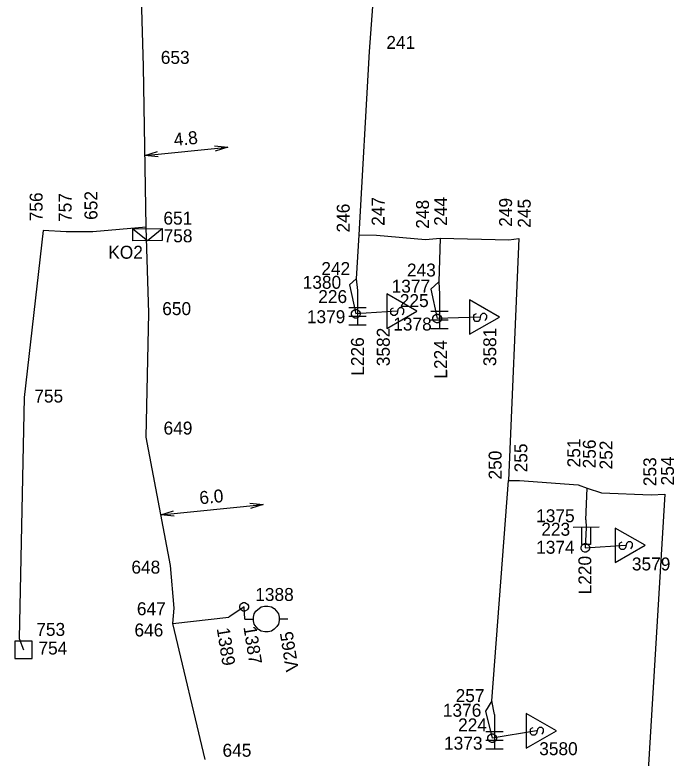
# Model space of a CAD drawing. Extents: x -535557 to -534097, y -1142175 to -1136716.
# Drawn here: x -534537.76 to -534499.53, y -1140603.81 to -1140560.72 of the extents above; entities that cross this region are included whole.
import ezdxf

# ---------------------------------------------------------------- set-up
doc = ezdxf.new("R2010")
doc.units = 0
doc.layers.add('Default', color=7, linetype='Continuous')
doc.layers.add('SS_SZDC', color=7, linetype='Continuous')

# ---------------------------------------------------------------- blocks, each defined once
blk = doc.blocks.new('POINT_DISPLAY')
at = {"layer": 'Default'}
blk.add_line((0, 0), (0, 0), dxfattribs=at)

msp = doc.modelspace()

# ---------------------------------------------------------------- linework, layer by layer
at = {"layer": 'SS_SZDC'}
for p, q in [((-534516.34, -1140551.12), (-534517.22, -1140562.84)), ((-534530.3, -1140563.709), (-534530.6, -1140554.11)), ((-534517.22, -1140562.84), (-534517.819, -1140573.469)), ((-534530.149, -1140573.03), (-534530.3, -1140563.709)), ((-534530.216, -1140568.872), (-534525.42, -1140568.396)), ((-534526.182, -1140568.32), (-534525.42, -1140568.396)), ((-534525.42, -1140568.396), (-534526.152, -1140568.619)), ((-534530.216, -1140568.872), (-534529.485, -1140568.648)), ((-534529.455, -1140568.947), (-534530.216, -1140568.872)), ((-534530.149, -1140573.03), (-534533.239, -1140573.29)), ((-534530.922, -1140573.115), (-534529.222, -1140573.104)), ((-534530.917, -1140573.815), (-534530.922, -1140573.115)), ((-534530.922, -1140573.115), (-534530.067, -1140573.809)), ((-534530, -1140578.01), (-534530.149, -1140573.03)), ((-534530.067, -1140573.809), (-534529.222, -1140573.104)), ((-534529.222, -1140573.104), (-534529.217, -1140573.804)), ((-534536.13, -1140573.219), (-534537.229, -1140582.909)), ((-534534.779, -1140573.29), (-534536.13, -1140573.219)), ((-534533.239, -1140573.29), (-534534.779, -1140573.29)), ((-534517.819, -1140573.469), (-534517.96, -1140576.02)), ((-534517.819, -1140573.469), (-534516.8, -1140573.489)), ((-534516.8, -1140573.489), (-534513.949, -1140573.75)), ((-534529.217, -1140573.804), (-534530.917, -1140573.815)), ((-534513.949, -1140573.75), (-534513.09, -1140573.67)), ((-534513.09, -1140573.67), (-534513.17, -1140576.19)), ((-534513.09, -1140573.67), (-534509.119, -1140573.76)), ((-534508.539, -1140573.68), (-534509.13, -1140587.719)), ((-534509.119, -1140573.76), (-534508.539, -1140573.68)), ((-534517.96, -1140576.02), (-534518.359, -1140576.36)), ((-534517.96, -1140576.02), (-534517.899, -1140576.7)), ((-534518.359, -1140576.36), (-534517.989, -1140578.049)), ((-534513.17, -1140576.19), (-534513.64, -1140576.629)), ((-534513.17, -1140576.19), (-534513.14, -1140576.92)), ((-534517.899, -1140576.7), (-534517.899, -1140578.7)), ((-534516.2, -1140576.899), (-534516.2, -1140578.899)), ((-534514.45, -1140577.899), (-534516.2, -1140576.899)), ((-534513.64, -1140576.629), (-534513.27, -1140578.319)), ((-534513.14, -1140576.92), (-534513.14, -1140578.92)), ((-534511.4, -1140577.239), (-534511.4, -1140579.239)), ((-534509.65, -1140578.239), (-534511.4, -1140577.239)), ((-534517.399, -1140577.7), (-534518.399, -1140577.7)), ((-534518.19, -1140577.901), (-534518.141, -1140577.85)), ((-534518.141, -1140577.85), (-534518.041, -1140577.8)), ((-534518.041, -1140577.8), (-534517.941, -1140577.799)), ((-534515.6, -1140577.899), (-534517.989, -1140578.049)), ((-534517.941, -1140577.799), (-534517.841, -1140577.849)), ((-534517.841, -1140577.849), (-534517.79, -1140577.898)), ((-534517.79, -1140577.898), (-534517.74, -1140577.998)), ((-534516.2, -1140578.899), (-534514.45, -1140577.899)), ((-534515.95, -1140577.799), (-534515.9, -1140577.749)), ((-534515.95, -1140578.049), (-534515.95, -1140577.799)), ((-534515.9, -1140577.749), (-534515.8, -1140577.699)), ((-534515.55, -1140577.799), (-534515.6, -1140578.049)), ((-534515.45, -1140577.699), (-534515.55, -1140577.799)), ((-534515.3, -1140577.699), (-534515.45, -1140577.699)), ((-534515.2, -1140577.799), (-534515.3, -1140577.699)), ((-534515.2, -1140577.949), (-534515.2, -1140577.799)), ((-534530.14, -1140585.2), (-534530, -1140578.01)), ((-534517.399, -1140578.2), (-534518.399, -1140578.2)), ((-534518.24, -1140578.001), (-534518.19, -1140577.901)), ((-534518.239, -1140578.101), (-534518.24, -1140578.001)), ((-534518.189, -1140578.201), (-534518.239, -1140578.101)), ((-534518.138, -1140578.25), (-534518.189, -1140578.201)), ((-534518.038, -1140578.3), (-534518.138, -1140578.25)), ((-534517.938, -1140578.299), (-534518.038, -1140578.3)), ((-534517.838, -1140578.249), (-534517.938, -1140578.299)), ((-534517.789, -1140578.198), (-534517.838, -1140578.249)), ((-534517.739, -1140578.098), (-534517.789, -1140578.198)), ((-534517.74, -1140577.998), (-534517.739, -1140578.098)), ((-534515.85, -1140578.149), (-534515.95, -1140578.049)), ((-534515.7, -1140578.149), (-534515.85, -1140578.149)), ((-534515.6, -1140578.049), (-534515.7, -1140578.149)), ((-534515.3, -1140578.099), (-534515.25, -1140578.049)), ((-534515.25, -1140578.049), (-534515.2, -1140577.949)), ((-534512.64, -1140577.92), (-534513.64, -1140577.92)), ((-534513.52, -1140578.271), (-534513.47, -1140578.171)), ((-534513.519, -1140578.371), (-534513.52, -1140578.271)), ((-534513.47, -1140578.171), (-534513.421, -1140578.12)), ((-534513.421, -1140578.12), (-534513.321, -1140578.07)), ((-534513.321, -1140578.07), (-534513.221, -1140578.069)), ((-534510.8, -1140578.239), (-534513.27, -1140578.319)), ((-534513.221, -1140578.069), (-534513.121, -1140578.119)), ((-534513.121, -1140578.119), (-534513.07, -1140578.168)), ((-534513.07, -1140578.168), (-534513.02, -1140578.268)), ((-534513.02, -1140578.268), (-534513.019, -1140578.368)), ((-534511.4, -1140579.239), (-534509.65, -1140578.239)), ((-534511.15, -1140578.139), (-534511.1, -1140578.089)), ((-534511.15, -1140578.389), (-534511.15, -1140578.139)), ((-534511.1, -1140578.089), (-534511, -1140578.039)), ((-534510.75, -1140578.139), (-534510.8, -1140578.389)), ((-534510.65, -1140578.039), (-534510.75, -1140578.139)), ((-534510.5, -1140578.039), (-534510.65, -1140578.039)), ((-534510.4, -1140578.139), (-534510.5, -1140578.039)), ((-534510.45, -1140578.389), (-534510.4, -1140578.289)), ((-534510.4, -1140578.289), (-534510.4, -1140578.139)), ((-534517.399, -1140578.7), (-534518.399, -1140578.7)), ((-534512.64, -1140578.42), (-534513.64, -1140578.42)), ((-534513.469, -1140578.471), (-534513.519, -1140578.371)), ((-534513.418, -1140578.52), (-534513.469, -1140578.471)), ((-534513.318, -1140578.57), (-534513.418, -1140578.52)), ((-534513.218, -1140578.569), (-534513.318, -1140578.57)), ((-534513.118, -1140578.519), (-534513.218, -1140578.569)), ((-534513.069, -1140578.468), (-534513.118, -1140578.519)), ((-534513.019, -1140578.368), (-534513.069, -1140578.468)), ((-534511.05, -1140578.489), (-534511.15, -1140578.389)), ((-534510.9, -1140578.489), (-534511.05, -1140578.489)), ((-534510.8, -1140578.389), (-534510.9, -1140578.489)), ((-534510.5, -1140578.439), (-534510.45, -1140578.389)), ((-534512.64, -1140578.92), (-534513.64, -1140578.92)), ((-534537.229, -1140582.909), (-534537.52, -1140596.87)), ((-534528.739, -1140592.639), (-534530.14, -1140585.2)), ((-534510.1, -1140600.479), (-534509.13, -1140587.719)), ((-534509.13, -1140587.719), (-534508.489, -1140587.719)), ((-534508.489, -1140587.719), (-534505.09, -1140587.959)), ((-534505.09, -1140587.959), (-534504.579, -1140588.159)), ((-534504.659, -1140589.989), (-534504.579, -1140588.159)), ((-534504.579, -1140588.159), (-534503.739, -1140588.43)), ((-534503.739, -1140588.43), (-534500.869, -1140588.54)), ((-534500.069, -1140588.51), (-534501.09, -1140605.28)), ((-534500.869, -1140588.54), (-534500.069, -1140588.51)), ((-534524.131, -1140589.037), (-534523.369, -1140589.113)), ((-534529.293, -1140589.697), (-534523.369, -1140589.113)), ((-534529.293, -1140589.697), (-534528.562, -1140589.474)), ((-534523.369, -1140589.113), (-534524.101, -1140589.336)), ((-534528.532, -1140589.772), (-534529.293, -1140589.697)), ((-534504.659, -1140589.989), (-534504.63, -1140590.43)), ((-534503.88, -1140590.425), (-534505.379, -1140590.434)), ((-534504.873, -1140591.431), (-534504.879, -1140590.431)), ((-534504.63, -1140590.43), (-534504.68, -1140591.62)), ((-534504.38, -1140590.428), (-534504.373, -1140591.428)), ((-534502.95, -1140590.469), (-534502.95, -1140592.469)), ((-534501.2, -1140591.469), (-534502.95, -1140590.469)), ((-534504.93, -1140591.571), (-534504.88, -1140591.471)), ((-534504.929, -1140591.671), (-534504.93, -1140591.571)), ((-534504.879, -1140591.771), (-534504.929, -1140591.671)), ((-534504.88, -1140591.471), (-534504.831, -1140591.42)), ((-534504.373, -1140591.428), (-534504.873, -1140591.431)), ((-534504.831, -1140591.42), (-534504.731, -1140591.37)), ((-534504.731, -1140591.37), (-534504.631, -1140591.369)), ((-534504.68, -1140591.62), (-534502.35, -1140591.469)), ((-534504.631, -1140591.369), (-534504.531, -1140591.419)), ((-534504.531, -1140591.419), (-534504.48, -1140591.468)), ((-534504.48, -1140591.468), (-534504.43, -1140591.568)), ((-534504.429, -1140591.668), (-534504.479, -1140591.768)), ((-534504.43, -1140591.568), (-534504.429, -1140591.668)), ((-534502.95, -1140592.469), (-534501.2, -1140591.469)), ((-534502.7, -1140591.369), (-534502.65, -1140591.319)), ((-534502.7, -1140591.619), (-534502.7, -1140591.369)), ((-534502.6, -1140591.719), (-534502.7, -1140591.619)), ((-534502.65, -1140591.319), (-534502.55, -1140591.269)), ((-534502.35, -1140591.619), (-534502.45, -1140591.719)), ((-534502.3, -1140591.369), (-534502.35, -1140591.619)), ((-534502.2, -1140591.269), (-534502.3, -1140591.369)), ((-534502.05, -1140591.269), (-534502.2, -1140591.269)), ((-534501.95, -1140591.369), (-534502.05, -1140591.269)), ((-534502.05, -1140591.669), (-534502, -1140591.619)), ((-534502, -1140591.619), (-534501.95, -1140591.519)), ((-534501.95, -1140591.519), (-534501.95, -1140591.369)), ((-534504.828, -1140591.82), (-534504.879, -1140591.771)), ((-534504.728, -1140591.87), (-534504.828, -1140591.82)), ((-534504.628, -1140591.869), (-534504.728, -1140591.87)), ((-534504.528, -1140591.819), (-534504.628, -1140591.869)), ((-534504.479, -1140591.768), (-534504.528, -1140591.819)), ((-534502.45, -1140591.719), (-534502.6, -1140591.719)), ((-534528.529, -1140595.12), (-534528.739, -1140592.639)), ((-534528.6, -1140596), (-534528.529, -1140595.12)), ((-534524.47, -1140595.04), (-534525.35, -1140595.629)), ((-534524.72, -1140594.991), (-534524.67, -1140594.891)), ((-534524.719, -1140595.091), (-534524.72, -1140594.991)), ((-534524.669, -1140595.191), (-534524.719, -1140595.091)), ((-534524.67, -1140594.891), (-534524.621, -1140594.84)), ((-534524.621, -1140594.84), (-534524.521, -1140594.79)), ((-534524.521, -1140594.79), (-534524.421, -1140594.789)), ((-534524.43, -1140595.75), (-534524.47, -1140595.04)), ((-534524.421, -1140594.789), (-534524.321, -1140594.839)), ((-534524.321, -1140594.839), (-534524.27, -1140594.888)), ((-534524.27, -1140594.888), (-534524.22, -1140594.988)), ((-534524.219, -1140595.088), (-534524.269, -1140595.188)), ((-534524.22, -1140594.988), (-534524.219, -1140595.088)), ((-534523.782, -1140595.295), (-534523.484, -1140595.043)), ((-534523.484, -1140595.043), (-534523.284, -1140594.992)), ((-534523.284, -1140594.992), (-534523.084, -1140594.991)), ((-534523.084, -1140594.991), (-534522.884, -1140595.039)), ((-534522.884, -1140595.039), (-534522.733, -1140595.138)), ((-534524.618, -1140595.24), (-534524.669, -1140595.191)), ((-534524.518, -1140595.29), (-534524.618, -1140595.24)), ((-534524.418, -1140595.289), (-534524.518, -1140595.29)), ((-534524.318, -1140595.239), (-534524.418, -1140595.289)), ((-534524.269, -1140595.188), (-534524.318, -1140595.239)), ((-534523.93, -1140595.646), (-534523.881, -1140595.446)), ((-534523.881, -1140595.446), (-534523.782, -1140595.295)), ((-534522.733, -1140595.138), (-534522.582, -1140595.287)), ((-534522.582, -1140595.287), (-534522.482, -1140595.437)), ((-534522.482, -1140595.437), (-534522.43, -1140595.636)), ((-534528.6, -1140596), (-534525.35, -1140595.629)), ((-534524.43, -1140595.75), (-534523.93, -1140595.746)), ((-534523.93, -1140595.746), (-534523.93, -1140595.646)), ((-534523.929, -1140595.846), (-534523.93, -1140595.746)), ((-534523.878, -1140596.046), (-534523.929, -1140595.846)), ((-534522.429, -1140595.836), (-534522.478, -1140596.037)), ((-534522.43, -1140595.636), (-534522.429, -1140595.836)), ((-534522.43, -1140595.736), (-534521.93, -1140595.733)), ((-534526.72, -1140603.879), (-534528.6, -1140596)), ((-534523.777, -1140596.195), (-534523.878, -1140596.046)), ((-534523.626, -1140596.344), (-534523.777, -1140596.195)), ((-534523.475, -1140596.443), (-534523.626, -1140596.344)), ((-534522.726, -1140596.338), (-534522.875, -1140596.439)), ((-534522.577, -1140596.187), (-534522.726, -1140596.338)), ((-534522.478, -1140596.037), (-534522.577, -1140596.187)), ((-534523.275, -1140596.492), (-534523.475, -1140596.443)), ((-534523.075, -1140596.491), (-534523.275, -1140596.492)), ((-534522.875, -1140596.439), (-534523.075, -1140596.491)), ((-534536.763, -1140597.026), (-534537.763, -1140597.033)), ((-534537.763, -1140597.033), (-534537.756, -1140598.033)), ((-534537.52, -1140596.87), (-534537.26, -1140597.53)), ((-534536.756, -1140598.026), (-534536.763, -1140597.026)), ((-534537.756, -1140598.033), (-534536.756, -1140598.026)), ((-534510.1, -1140600.479), (-534510.46, -1140601.09)), ((-534509.949, -1140601.28), (-534510.1, -1140600.479)), ((-534510.46, -1140601.09), (-534510.079, -1140602.649)), ((-534509.949, -1140601.28), (-534509.949, -1140603.28)), ((-534508.11, -1140601.229), (-534508.11, -1140603.229)), ((-534506.36, -1140602.229), (-534508.11, -1140601.229)), ((-534507.81, -1140602.079), (-534507.71, -1140602.029)), ((-534507.36, -1140602.029), (-534507.46, -1140602.129)), ((-534507.21, -1140602.029), (-534507.36, -1140602.029)), ((-534507.11, -1140602.129), (-534507.21, -1140602.029)), ((-534509.449, -1140602.28), (-534510.449, -1140602.28)), ((-534510.28, -1140602.501), (-534510.231, -1140602.45)), ((-534510.231, -1140602.45), (-534510.131, -1140602.4)), ((-534510.131, -1140602.4), (-534510.031, -1140602.399)), ((-534507.51, -1140602.229), (-534510.079, -1140602.649)), ((-534510.031, -1140602.399), (-534509.931, -1140602.449)), ((-534509.931, -1140602.449), (-534509.88, -1140602.498)), ((-534508.11, -1140603.229), (-534506.36, -1140602.229)), ((-534507.86, -1140602.129), (-534507.81, -1140602.079)), ((-534507.86, -1140602.379), (-534507.86, -1140602.129)), ((-534507.76, -1140602.479), (-534507.86, -1140602.379)), ((-534507.51, -1140602.379), (-534507.61, -1140602.479)), ((-534507.46, -1140602.129), (-534507.51, -1140602.379)), ((-534507.21, -1140602.429), (-534507.16, -1140602.379)), ((-534507.16, -1140602.379), (-534507.11, -1140602.279)), ((-534507.11, -1140602.279), (-534507.11, -1140602.129)), ((-534509.449, -1140602.78), (-534510.449, -1140602.78)), ((-534510.33, -1140602.601), (-534510.28, -1140602.501)), ((-534510.329, -1140602.701), (-534510.33, -1140602.601)), ((-534510.279, -1140602.801), (-534510.329, -1140602.701)), ((-534510.228, -1140602.85), (-534510.279, -1140602.801)), ((-534510.128, -1140602.9), (-534510.228, -1140602.85)), ((-534509.928, -1140602.849), (-534510.028, -1140602.899)), ((-534509.879, -1140602.798), (-534509.928, -1140602.849)), ((-534509.88, -1140602.498), (-534509.83, -1140602.598)), ((-534509.829, -1140602.698), (-534509.879, -1140602.798)), ((-534509.83, -1140602.598), (-534509.829, -1140602.698)), ((-534507.61, -1140602.479), (-534507.76, -1140602.479)), ((-534509.449, -1140603.28), (-534510.449, -1140603.28)), ((-534510.028, -1140602.899), (-534510.128, -1140602.9))]:
    msp.add_line(p, q, dxfattribs=at)

# ---------------------------------------------------------------- block references
for p in [(-534517.22, -1140562.84), (-534530.3, -1140563.709), (-534530.149, -1140573.03), (-534536.13, -1140573.219), (-534534.779, -1140573.29), (-534533.239, -1140573.29), (-534530.069, -1140573.459), (-534517.819, -1140573.469), (-534516.8, -1140573.489), (-534513.949, -1140573.75), (-534513.09, -1140573.67), (-534509.119, -1140573.76), (-534508.539, -1140573.68), (-534517.96, -1140576.02), (-534518.359, -1140576.36), (-534513.17, -1140576.19), (-534517.899, -1140576.7), (-534513.64, -1140576.629), (-534513.14, -1140576.92), (-534515.6, -1140577.899), (-534530, -1140578.01), (-534517.989, -1140578.049), (-534517.989, -1140578.049), (-534513.27, -1140578.319), (-534513.27, -1140578.319), (-534510.8, -1140578.239), (-534537.229, -1140582.909), (-534530.14, -1140585.2), (-534509.13, -1140587.719), (-534508.489, -1140587.719), (-534505.09, -1140587.959), (-534504.579, -1140588.159), (-534503.739, -1140588.43), (-534500.869, -1140588.54), (-534500.069, -1140588.51), (-534504.659, -1140589.989), (-534504.63, -1140590.43), (-534504.68, -1140591.62), (-534504.68, -1140591.62), (-534502.35, -1140591.469), (-534528.739, -1140592.639), (-534528.529, -1140595.12), (-534524.47, -1140595.04), (-534524.47, -1140595.04), (-534525.35, -1140595.629), (-534524.43, -1140595.75), (-534528.6, -1140596), (-534537.52, -1140596.87), (-534537.26, -1140597.53), (-534510.1, -1140600.479), (-534510.46, -1140601.09), (-534509.949, -1140601.28), (-534507.51, -1140602.229), (-534510.079, -1140602.649), (-534510.079, -1140602.649)]:
    msp.add_blockref('POINT_DISPLAY', p, dxfattribs=at)

# ---------------------------------------------------------------- texts
for s, p in [('241', (-534516.22, -1140562.69)), ('653', (-534529.3, -1140563.559)), ('651', (-534529.149, -1140572.88)), ('758', (-534529.136, -1140573.904)), ('KO2', (-534532.346, -1140574.856)), ('242', (-534519.99, -1140575.798)), ('243', (-534515.024, -1140575.886)), ('1380', (-534521.07, -1140576.598)), ('1377', (-534515.913, -1140576.823)), ('226', (-534520.168, -1140577.424)), ('225', (-534515.438, -1140577.658)), ('650', (-534529.216, -1140578.123)), ('1379', (-534520.829, -1140578.592)), ('1378', (-534515.82, -1140579.019)), ('755', (-534536.635, -1140583.193)), ('649', (-534529.14, -1140585.05)), ('1375', (-534507.531, -1140590.132)), ('223', (-534507.233, -1140590.914)), ('1374', (-534507.531, -1140591.958)), ('648', (-534531.004, -1140593.111)), ('3579', (-534501.979, -1140592.927)), ('1388', (-534523.822, -1140594.696)), ('647', (-534530.687, -1140595.523)), ('753', (-534536.52, -1140596.72)), ('646', (-534530.828, -1140596.755)), ('754', (-534536.395, -1140597.802)), ('257', (-534512.2, -1140600.559)), ('1376', (-534512.943, -1140601.408)), ('224', (-534512.059, -1140602.257)), ('1373', (-534512.873, -1140603.318)), ('3580', (-534507.354, -1140603.637)), ('645', (-534525.72, -1140603.729))]:
    msp.add_text(s, height=0.75, dxfattribs=at).set_placement(p)
for s, rotation, p in [('4.8', 5.6664, (-534528.513, -1140568.326)), ('652', 90, (-534532.976, -1140572.604)), ('756', 90, (-534536.155, -1140572.684)), ('757', 90, (-534534.475, -1140572.724)), ('247', 90, (-534516.323, -1140572.95)), ('244', 90, (-534512.695, -1140572.95)), ('249', 90, (-534508.928, -1140573.005)), ('245', 90, (-534507.848, -1140573.061)), ('246', 90, (-534518.345, -1140573.337)), ('248', 90, (-534513.747, -1140573.116)), ('3582', 90, (-534516.022, -1140581.087)), ('3581', 90, (-534509.846, -1140581.087)), ('L226', 90.3756, (-534517.508, -1140581.639)), ('L224', 90.3756, (-534512.689, -1140581.807)), ('255', 90, (-534508.042, -1140587.241)), ('251', 90, (-534504.975, -1140586.953)), ('256', 90, (-534504.074, -1140587.01)), ('252', 90, (-534503.105, -1140587.073)), ('250', 90, (-534509.537, -1140587.656)), ('253', 90, (-534500.564, -1140588.044)), ('254', 90, (-534499.54, -1140587.998)), ('6.0', 5.63, (-534527.026, -1140589.096)), ('L220', 90.3756, (-534504.322, -1140594.314)), ('1389', 279, (-534526.058, -1140596.297)), ('1387', 279, (-534524.509, -1140596.209)), ('V265', 99, (-534521.293, -1140598.732))]:
    msp.add_text(s, height=0.75, rotation=rotation, dxfattribs=at).set_placement(p)

doc.saveas('drawing.dxf')
